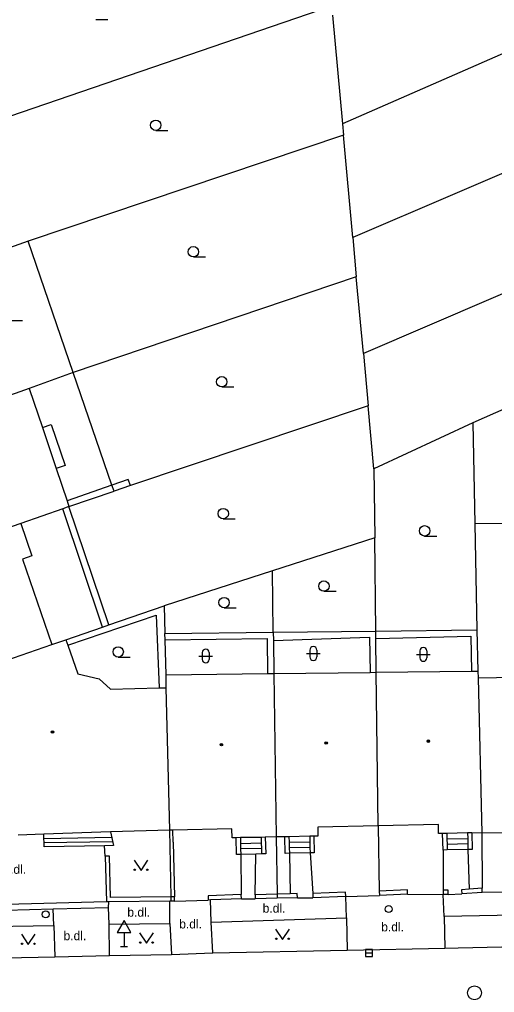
# Model space of a CAD drawing. Extents: x -596229 to -595156, y -1161237 to -1159376.
# Drawn here: x -595820.2 to -595785.9, y -1160892.5 to -1160822.2 of the extents above; entities that cross this region are included whole.
import ezdxf

# ---------------------------------------------------------------- set-up
doc = ezdxf.new("R2010")
doc.units = 0
for name, color, linetype in [('DOP - kresba z DSPS bez souradnic', 7, 'Continuous'), ('DOP - rozhrani ploch obecne', 7, 'Continuous'), ('Level 27', 7, 'Continuous'), ('Level 28', 7, 'Continuous'), ('Level 34', 7, 'Continuous'), ('Level 36', 7, 'Continuous'), ('Level 39', 7, 'Continuous'), ('Specificka linie pasportu komunikaci', 7, 'Continuous'), ('TM - budovy zdene_ betonove - VP', 7, 'Continuous'), ('TM - chodniky - VP', 7, 'Continuous'), ('TM - komunikace - VP', 7, 'Continuous'), ('TM - letecke snimky - pomocna linie', 7, 'Continuous'), ('TM - plot drateny_ kovovy - VP', 7, 'Continuous'), ('TM - plot dreveny - VP', 7, 'Continuous'), ('TM - podezdivka plotu - VP', 7, 'Continuous'), ('TM - popis povrchu', 7, 'Continuous'), ('TM - rozhrani mezi zpev. plochami mezi sebou - VP', 7, 'Continuous'), ('TM - rozhrani ploch obecne - VP', 7, 'Continuous'), ('TM - schody - VP', 7, 'Continuous'), ('TM - vjezd na pozemek', 7, 'Continuous')]:
    doc.layers.add(name, color=color, linetype=linetype)

msp = doc.modelspace()

# ---------------------------------------------------------------- linework, layer by layer
at = {"layer": 'DOP - kresba z DSPS bez souradnic'}
for points in [[(-595818.58, -1160851.68), (-595817.94, -1160851.46)], [(-595817.94, -1160851.46), (-595816.93, -1160854.44)], [(-595816.93, -1160854.44), (-595817.58, -1160854.66)], [(-595812.37, -1160855.45), (-595813.55, -1160855.86)], [(-595812.22, -1160855.88), (-595812.37, -1160855.45)], [(-595813.55, -1160855.86), (-595816.8, -1160856.98)], [(-595814.24, -1160866.1), (-595817.11, -1160857.56)], [(-595816.75, -1160867.41), (-595810.35, -1160865.24)], [(-595810.35, -1160865.24), (-595810.14, -1160870.5)], [(-595801.88, -1160867.08), (-595794.93, -1160866.84)], [(-595794.93, -1160866.84), (-595794.9, -1160869.38)], [(-595809.71, -1160867.02), (-595802.34, -1160866.93)], [(-595802.34, -1160866.93), (-595802.31, -1160869.47)]]:
    msp.add_lwpolyline(points, dxfattribs=at)
at = {"layer": 'DOP - rozhrani ploch obecne'}
for points in [[(-595777.01, -1160821.04), (-595796.9, -1160829.74)], [(-595825.24, -1160830.65), (-595797.67, -1160821.23)], [(-595797.61, -1160821.89), (-595796.9, -1160829.74)], [(-595774.54, -1160828.72), (-595796.14, -1160837.97)], [(-595796.9, -1160829.74), (-595796.82, -1160830.57)], [(-595796.82, -1160830.57), (-595819.62, -1160838.22)], [(-595796.14, -1160837.97), (-595796.82, -1160830.57)], [(-595772.03, -1160836.33), (-595795.38, -1160846.35)], [(-595796.14, -1160837.97), (-595795.89, -1160840.79)], [(-595819.62, -1160838.22), (-595822.27, -1160839.17)], [(-595816.35, -1160847.72), (-595819.62, -1160838.22)], [(-595795.89, -1160840.79), (-595816.35, -1160847.72)], [(-595795.38, -1160846.35), (-595795.89, -1160840.79)], [(-595795.38, -1160846.35), (-595795.03, -1160850.13)], [(-595816.35, -1160847.72), (-595819.53, -1160848.87)], [(-595813.55, -1160855.86), (-595816.35, -1160847.72)], [(-595779.88, -1160847.99), (-595787.48, -1160851.34)], [(-595795.03, -1160850.13), (-595812.22, -1160855.88)], [(-595794.62, -1160854.67), (-595795.03, -1160850.13)], [(-595787.48, -1160851.34), (-595794.62, -1160854.67)], [(-595787.48, -1160851.34), (-595787.33, -1160858.64)], [(-595794.62, -1160854.67), (-595794.56, -1160859.66)], [(-595816.66, -1160857.4), (-595813.4, -1160856.28)], [(-595813.4, -1160856.28), (-595813.55, -1160855.86)], [(-595812.22, -1160855.88), (-595813.4, -1160856.28)], [(-595813.78, -1160865.94), (-595816.66, -1160857.4)], [(-595794.56, -1160859.66), (-595801.95, -1160862.04)], [(-595794.48, -1160866.39), (-595794.56, -1160859.66)], [(-595801.95, -1160862.04), (-595809.78, -1160864.56)], [(-595801.89, -1160866.48), (-595801.95, -1160862.04)], [(-595813.78, -1160865.94), (-595809.78, -1160864.56)], [(-595809.78, -1160864.56), (-595809.72, -1160866.57)], [(-595816.89, -1160867.02), (-595814.24, -1160866.1)], [(-595814.24, -1160866.1), (-595813.78, -1160865.94)], [(-595809.72, -1160866.57), (-595801.89, -1160866.48)], [(-595809.71, -1160867.02), (-595809.72, -1160866.57)], [(-595801.89, -1160866.48), (-595794.48, -1160866.39)], [(-595801.89, -1160866.48), (-595801.88, -1160867.08)], [(-595794.47, -1160866.92), (-595794.48, -1160866.39)], [(-595809.64, -1160869.55), (-595809.71, -1160867.02)], [(-595801.88, -1160867.08), (-595801.85, -1160869.46)], [(-595794.45, -1160869.37), (-595794.47, -1160866.92)]]:
    msp.add_lwpolyline(points, dxfattribs=at)
at = {"layer": 'Level 27'}
msp.add_line((-595795.22, -1160889.65), (-595794.72, -1160889.65), dxfattribs=at)
msp.add_lwpolyline([(-595795.22, -1160889.9), (-595794.72, -1160889.9), (-595794.72, -1160889.4), (-595795.22, -1160889.4)], close=True, dxfattribs=at)
msp.add_circle((-595787.35, -1160892.53), 0.5, dxfattribs=at)
at = {"layer": 'Level 28'}
for centre in [(-595793.55, -1160886.48), (-595818.34, -1160886.86)]:
    msp.add_circle(centre, 0.25, dxfattribs=at)
at = {"layer": 'Level 34'}
for p, q in [((-595812.68, -1160888.172), (-595812.68, -1160889.19)), ((-595812.93, -1160889.19), (-595812.43, -1160889.19))]:
    msp.add_line(p, q, dxfattribs=at)
msp.add_lwpolyline([(-595813.18, -1160888.172), (-595812.18, -1160888.172), (-595812.68, -1160887.306)], close=True, dxfattribs=at)
at = {"layer": 'Level 36'}
for p, q in [((-595814.72, -1160822.205), (-595813.845, -1160822.205)), ((-595810.39, -1160830.225), (-595809.515, -1160830.225)), ((-595807.67, -1160839.365), (-595806.795, -1160839.365)), ((-595821.016, -1160843.956), (-595820.016, -1160843.956)), ((-595805.62, -1160848.755), (-595804.745, -1160848.755)), ((-595805.51, -1160858.285), (-595804.635, -1160858.285)), ((-595790.95, -1160859.525), (-595790.075, -1160859.525)), ((-595798.23, -1160863.515), (-595797.355, -1160863.515)), ((-595805.45, -1160864.715), (-595804.575, -1160864.715)), ((-595813.1, -1160868.275), (-595812.225, -1160868.275)), ((-595807.276, -1160868.196), (-595806.276, -1160868.196)), ((-595807.026, -1160867.946), (-595807.026, -1160868.446)), ((-595806.526, -1160867.946), (-595806.526, -1160868.446)), ((-595799.496, -1160868.016), (-595798.496, -1160868.016)), ((-595799.246, -1160867.766), (-595799.246, -1160868.266)), ((-595798.746, -1160867.766), (-595798.746, -1160868.266)), ((-595791.546, -1160868.076), (-595790.546, -1160868.076)), ((-595791.296, -1160867.826), (-595791.296, -1160868.326)), ((-595790.796, -1160867.826), (-595790.796, -1160868.326))]:
    msp.add_line(p, q, dxfattribs=at)
for points in [[(-595811.95, -1160882.94), (-595811.45, -1160883.69), (-595810.95, -1160882.94)], [(-595801.72, -1160887.92), (-595801.22, -1160888.67), (-595800.72, -1160887.92)], [(-595820.1, -1160888.29), (-595819.6, -1160889.04), (-595819.1, -1160888.29)], [(-595811.56, -1160888.2), (-595811.06, -1160888.95), (-595810.56, -1160888.2)]]:
    msp.add_lwpolyline(points, dxfattribs=at)
for centre, radius in [((-595810.39, -1160829.85), 0.375), ((-595807.67, -1160838.99), 0.375), ((-595805.62, -1160848.38), 0.375), ((-595805.51, -1160857.91), 0.375), ((-595790.95, -1160859.15), 0.375), ((-595798.23, -1160863.14), 0.375), ((-595805.45, -1160864.34), 0.375), ((-595813.1, -1160867.9), 0.375), ((-595811.9, -1160883.64), 0.05), ((-595811.001, -1160883.64), 0.05), ((-595801.67, -1160888.62), 0.05), ((-595800.771, -1160888.62), 0.05), ((-595820.05, -1160888.99), 0.05), ((-595819.151, -1160888.99), 0.05), ((-595811.51, -1160888.9), 0.05), ((-595810.611, -1160888.9), 0.05)]:
    msp.add_circle(centre, radius, dxfattribs=at)
for centre, start, end in [((-595798.996, -1160867.766), 0, 180), ((-595791.046, -1160867.826), 0, 180), ((-595806.776, -1160867.946), 0, 180), ((-595798.996, -1160868.266), 180, 0), ((-595806.776, -1160868.446), 180, 0), ((-595791.046, -1160868.326), 180, 0)]:
    msp.add_arc(centre, 0.25, start, end, dxfattribs=at)
at = {"layer": 'Level 39'}
for centre, radius in [((-595817.85, -1160873.68), 0.09), ((-595817.85, -1160873.68), 0.0398), ((-595805.64, -1160874.6), 0.09), ((-595805.64, -1160874.6), 0.0398), ((-595798.07, -1160874.48), 0.09), ((-595798.07, -1160874.48), 0.0398), ((-595790.68, -1160874.35), 0.09), ((-595790.68, -1160874.35), 0.0398)]:
    msp.add_circle(centre, radius, dxfattribs=at)
at = {"layer": 'Specificka linie pasportu komunikaci'}
for points in [[(-595809.13, -1160881.64), (-595809.15, -1160880.77)], [(-595809.13, -1160881.64), (-595809.04, -1160885.6)]]:
    msp.add_lwpolyline(points, dxfattribs=at)
at = {"layer": 'TM - budovy zdene_ betonove - VP'}
for points in [[(-595819.53, -1160848.87), (-595821.65, -1160849.62)], [(-595819.53, -1160848.87), (-595818.58, -1160851.68)], [(-595818.58, -1160851.68), (-595817.58, -1160854.66)], [(-595817.58, -1160854.66), (-595816.8, -1160856.98)], [(-595816.8, -1160856.98), (-595816.66, -1160857.4)], [(-595817.11, -1160857.56), (-595820.13, -1160858.62)], [(-595816.66, -1160857.4), (-595817.11, -1160857.56)], [(-595820.13, -1160858.62), (-595830.25, -1160862.12)], [(-595820.13, -1160858.62), (-595819.35, -1160860.96)], [(-595819.35, -1160860.96), (-595820.01, -1160861.19)], [(-595820.01, -1160861.19), (-595817.9, -1160867.37)], [(-595827.34, -1160870.63), (-595817.9, -1160867.37)], [(-595817.9, -1160867.37), (-595816.89, -1160867.02)], [(-595816.89, -1160867.02), (-595816.75, -1160867.41)], [(-595816.75, -1160867.41), (-595816.03, -1160869.49)], [(-595816.03, -1160869.49), (-595814.48, -1160869.85)], [(-595809.64, -1160869.55), (-595802.31, -1160869.47)], [(-595809.64, -1160870.49), (-595809.64, -1160869.55)], [(-595802.31, -1160869.47), (-595801.85, -1160869.46)], [(-595801.85, -1160869.46), (-595794.9, -1160869.38)], [(-595801.85, -1160869.46), (-595801.68, -1160881.27)], [(-595794.9, -1160869.38), (-595794.45, -1160869.37)], [(-595794.45, -1160869.37), (-595787.57, -1160869.29)], [(-595794.32, -1160880.46), (-595794.45, -1160869.37)], [(-595787.57, -1160869.29), (-595787.1, -1160869.28)], [(-595787.1, -1160869.28), (-595787.09, -1160869.78)], [(-595787.09, -1160869.78), (-595783.08, -1160869.71)], [(-595814.48, -1160869.85), (-595813.65, -1160870.59)], [(-595787.09, -1160869.78), (-595786.82, -1160881)], [(-595813.65, -1160870.59), (-595810.14, -1160870.5)], [(-595810.14, -1160870.5), (-595809.64, -1160870.49)], [(-595809.38, -1160880.77), (-595809.64, -1160870.49)], [(-595813.66, -1160880.9), (-595818.48, -1160881.07)], [(-595809.38, -1160880.77), (-595813.66, -1160880.9)], [(-595809.15, -1160880.77), (-595809.38, -1160880.77)], [(-595804.88, -1160880.68), (-595809.15, -1160880.77)], [(-595804.87, -1160881.34), (-595804.88, -1160880.68)], [(-595794.32, -1160880.46), (-595798.67, -1160880.55)], [(-595798.67, -1160880.55), (-595798.66, -1160881.21)], [(-595789.96, -1160880.37), (-595794.32, -1160880.46)], [(-595789.95, -1160881.02), (-595789.96, -1160880.37)], [(-595818.48, -1160881.07), (-595820.34, -1160881.14)], [(-595804.57, -1160881.33), (-595804.87, -1160881.34)], [(-595804.27, -1160881.32), (-595804.57, -1160881.33)], [(-595802.77, -1160881.3), (-595804.27, -1160881.32)], [(-595802.47, -1160881.29), (-595802.77, -1160881.3)], [(-595801.68, -1160881.27), (-595802.47, -1160881.29)], [(-595801.06, -1160881.26), (-595801.68, -1160881.27)], [(-595800.76, -1160881.25), (-595801.06, -1160881.26)], [(-595799.26, -1160881.22), (-595800.76, -1160881.25)], [(-595798.96, -1160881.21), (-595799.26, -1160881.22)], [(-595798.66, -1160881.21), (-595798.96, -1160881.21)], [(-595789.65, -1160881.02), (-595789.95, -1160881.02)], [(-595789.35, -1160881.01), (-595789.65, -1160881.02)], [(-595787.85, -1160880.98), (-595789.35, -1160881.01)], [(-595787.55, -1160880.97), (-595787.85, -1160880.98)], [(-595786.82, -1160881), (-595787.55, -1160880.97)], [(-595784.94, -1160880.96), (-595786.82, -1160881)]]:
    msp.add_lwpolyline(points, dxfattribs=at)
at = {"layer": 'TM - chodniky - VP'}
for points in [[(-595814.04, -1160882.66), (-595814.08, -1160881.9)], [(-595779.27, -1160885.16), (-595786.8, -1160885.28)], [(-595806.37, -1160887.42), (-595796.6, -1160887.12)], [(-595796.6, -1160887.12), (-595796.54, -1160889.45)], [(-595771.68, -1160888.9), (-595771.71, -1160886.69), (-595789.54, -1160887.02)], [(-595789.54, -1160887.02), (-595789.5, -1160889.3)], [(-595823.69, -1160889.54), (-595823.74, -1160887.77), (-595817.76, -1160887.66)], [(-595817.76, -1160887.66), (-595817.69, -1160889.93)], [(-595813.76, -1160887.58), (-595809.36, -1160887.52)], [(-595813.73, -1160889.84), (-595813.76, -1160887.58)], [(-595809.36, -1160887.52), (-595809.25, -1160889.75)], [(-595806.27, -1160889.64), (-595806.37, -1160887.42)]]:
    msp.add_lwpolyline(points, dxfattribs=at)
at = {"layer": 'TM - komunikace - VP'}
for points in [[(-595796.54, -1160889.45), (-595789.5, -1160889.3)], [(-595789.5, -1160889.3), (-595788.52, -1160889.27), (-595771.68, -1160888.9)], [(-595823.71, -1160890.05), (-595817.69, -1160889.93)], [(-595817.69, -1160889.93), (-595813.73, -1160889.84)], [(-595813.73, -1160889.84), (-595809.25, -1160889.75)], [(-595809.25, -1160889.75), (-595806.27, -1160889.64)], [(-595806.27, -1160889.64), (-595796.54, -1160889.45)]]:
    msp.add_lwpolyline(points, dxfattribs=at)
at = {"layer": 'TM - letecke snimky - pomocna linie'}
for points in [[(-595789.62, -1160882.22), (-595789.61, -1160885.12)], [(-595787.82, -1160882.17), (-595787.74, -1160885.04)], [(-595804.24, -1160882.53), (-595804.21, -1160885.43)], [(-595803.2, -1160885.45), (-595803.16, -1160882.51)], [(-595800.73, -1160882.45), (-595800.66, -1160885.37)], [(-595799.23, -1160882.42), (-595799.04, -1160885.36)]]:
    msp.add_lwpolyline(points, dxfattribs=at)
at = {"layer": 'TM - plot drateny_ kovovy - VP'}
for points in [[(-595787.33, -1160858.64), (-595787.17, -1160866.3)], [(-595794.47, -1160866.92), (-595787.61, -1160866.76)], [(-595787.61, -1160866.76), (-595787.57, -1160869.29)], [(-595809.28, -1160885.6), (-595809.38, -1160880.77)], [(-595794.32, -1160880.46), (-595794.23, -1160885.19)], [(-595801.68, -1160881.27), (-595801.62, -1160885.4)], [(-595786.82, -1160881), (-595786.8, -1160884.98)], [(-595813.65, -1160885.65), (-595813.74, -1160882.65), (-595814.04, -1160882.66)], [(-595792.19, -1160885.4), (-595792.2, -1160885.1), (-595794.23, -1160885.19)], [(-595789.61, -1160885.12), (-595789.61, -1160885.42)], [(-595789.26, -1160885.42), (-595789.26, -1160885.12), (-595789.61, -1160885.12)], [(-595787.74, -1160885.04), (-595788.29, -1160885.08), (-595788.27, -1160885.38)], [(-595786.8, -1160884.98), (-595787.74, -1160885.04)], [(-595786.8, -1160885.28), (-595786.8, -1160884.98)], [(-595809.28, -1160885.6), (-595813.65, -1160885.65)], [(-595809.04, -1160885.6), (-595809.28, -1160885.6)], [(-595809.27, -1160885.9), (-595809.28, -1160885.6)], [(-595809.04, -1160885.9), (-595809.04, -1160885.6)], [(-595804.21, -1160885.43), (-595806.6, -1160885.53), (-595806.59, -1160885.83)], [(-595804.2, -1160885.73), (-595804.21, -1160885.43)], [(-595801.62, -1160885.4), (-595803.2, -1160885.45)], [(-595803.2, -1160885.45), (-595803.19, -1160885.75)], [(-595800.66, -1160885.37), (-595801.62, -1160885.4)], [(-595801.62, -1160885.4), (-595801.61, -1160885.7)], [(-595800.15, -1160885.66), (-595800.16, -1160885.36), (-595800.66, -1160885.37)], [(-595796.65, -1160885.57), (-595796.66, -1160885.27), (-595799.04, -1160885.36)], [(-595799.04, -1160885.36), (-595799.03, -1160885.66)], [(-595794.23, -1160885.19), (-595794.22, -1160885.49)]]:
    msp.add_lwpolyline(points, dxfattribs=at)
at = {"layer": 'TM - plot dreveny - VP'}
msp.add_lwpolyline([(-595779.87, -1160858.57), (-595787.33, -1160858.64)], dxfattribs=at)
at = {"layer": 'TM - podezdivka plotu - VP'}
for points in [[(-595794.48, -1160866.39), (-595787.17, -1160866.3)], [(-595787.17, -1160866.3), (-595787.1, -1160869.28)], [(-595814.04, -1160882.66), (-595813.94, -1160885.95)], [(-595806.44, -1160885.82), (-595806.59, -1160885.83)], [(-595804.2, -1160885.73), (-595806.44, -1160885.82)], [(-595801.61, -1160885.7), (-595803.19, -1160885.75)], [(-595800.15, -1160885.66), (-595801.61, -1160885.7)], [(-595796.65, -1160885.57), (-595799.03, -1160885.66)], [(-595792.19, -1160885.4), (-595794.22, -1160885.49)], [(-595789.26, -1160885.42), (-595789.61, -1160885.42)], [(-595786.8, -1160885.28), (-595788.27, -1160885.38)], [(-595813.78, -1160885.95), (-595813.94, -1160885.95)], [(-595809.36, -1160885.9), (-595813.78, -1160885.95)], [(-595809.27, -1160885.9), (-595809.36, -1160885.9)], [(-595809.04, -1160885.9), (-595809.27, -1160885.9)]]:
    msp.add_lwpolyline(points, dxfattribs=at)
at = {"layer": 'TM - rozhrani mezi zpev. plochami mezi sebou - VP'}
for points in [[(-595806.37, -1160887.42), (-595806.44, -1160885.82)], [(-595796.6, -1160887.12), (-595796.65, -1160885.57)], [(-595789.54, -1160887.02), (-595789.61, -1160885.42)], [(-595824.67, -1160886.65), (-595817.8, -1160886.46)], [(-595813.94, -1160885.95), (-595823.92, -1160886.22)], [(-595817.8, -1160886.46), (-595813.79, -1160886.36)], [(-595817.76, -1160887.66), (-595817.8, -1160886.46)], [(-595813.79, -1160886.36), (-595813.78, -1160885.95)], [(-595813.76, -1160887.58), (-595813.79, -1160886.36)], [(-595809.36, -1160887.52), (-595809.36, -1160885.9)]]:
    msp.add_lwpolyline(points, dxfattribs=at)
at = {"layer": 'TM - rozhrani ploch obecne - VP'}
for points in [[(-595813.66, -1160880.9), (-595813.44, -1160881.89), (-595814.08, -1160881.9)], [(-595814.08, -1160881.9), (-595818.45, -1160881.98), (-595818.48, -1160881.07)], [(-595804.24, -1160882.53), (-595804.55, -1160882.53), (-595804.57, -1160881.33)], [(-595804.27, -1160881.32), (-595804.26, -1160881.73), (-595804.25, -1160882.13), (-595804.24, -1160882.53)], [(-595802.77, -1160881.3), (-595802.76, -1160881.7), (-595802.75, -1160882.1), (-595802.74, -1160882.5)], [(-595802.47, -1160881.29), (-595802.44, -1160882.49), (-595802.74, -1160882.5)], [(-595800.73, -1160882.45), (-595801.03, -1160882.46), (-595801.06, -1160881.26)], [(-595800.76, -1160881.25), (-595800.75, -1160881.65), (-595800.74, -1160882.05), (-595800.73, -1160882.45)], [(-595799.26, -1160881.22), (-595799.25, -1160881.62), (-595799.24, -1160882.02), (-595799.23, -1160882.42)], [(-595798.96, -1160881.21), (-595798.93, -1160882.41), (-595799.23, -1160882.42)], [(-595789.62, -1160882.22), (-595789.65, -1160881.02)], [(-595789.35, -1160881.01), (-595789.34, -1160881.41), (-595789.33, -1160881.81), (-595789.32, -1160882.21)], [(-595787.85, -1160880.98), (-595787.84, -1160881.37), (-595787.83, -1160881.77), (-595787.82, -1160882.17)], [(-595787.55, -1160880.97), (-595787.52, -1160882.17), (-595787.82, -1160882.17)], [(-595789.32, -1160882.21), (-595789.62, -1160882.22)], [(-595787.82, -1160882.17), (-595789.32, -1160882.21)], [(-595803.16, -1160882.51), (-595804.24, -1160882.53)], [(-595802.74, -1160882.5), (-595803.16, -1160882.51)], [(-595799.23, -1160882.42), (-595800.73, -1160882.45)]]:
    msp.add_lwpolyline(points, dxfattribs=at)
at = {"layer": 'TM - schody - VP'}
for points in [[(-595818.47, -1160881.38), (-595813.57, -1160881.29)], [(-595818.46, -1160881.68), (-595813.51, -1160881.59)], [(-595800.75, -1160881.65), (-595799.25, -1160881.62)], [(-595789.34, -1160881.41), (-595787.84, -1160881.37)], [(-595804.26, -1160881.73), (-595802.76, -1160881.7)], [(-595802.75, -1160882.1), (-595804.25, -1160882.13)], [(-595799.24, -1160882.02), (-595800.74, -1160882.05)], [(-595787.83, -1160881.77), (-595789.33, -1160881.81)]]:
    msp.add_lwpolyline(points, dxfattribs=at)
at = {"layer": 'TM - vjezd na pozemek'}
for points in [[(-595809.04, -1160885.9), (-595806.59, -1160885.83)], [(-595804.2, -1160885.73), (-595803.19, -1160885.75)], [(-595800.15, -1160885.66), (-595799.03, -1160885.66)], [(-595796.65, -1160885.57), (-595794.22, -1160885.49)], [(-595792.19, -1160885.4), (-595789.61, -1160885.42)], [(-595789.26, -1160885.42), (-595788.27, -1160885.38)]]:
    msp.add_lwpolyline(points, dxfattribs=at)

# ---------------------------------------------------------------- texts
at = {"layer": 'TM - popis povrchu'}
for p in [(-595821.4, -1160883.93), (-595812.44, -1160887.03), (-595802.66, -1160886.74), (-595808.69, -1160887.88), (-595794.09, -1160888.09), (-595817.05, -1160888.73)]:
    msp.add_text('b.dl.', height=0.65, dxfattribs=at).set_placement(p)

doc.saveas('drawing.dxf')
